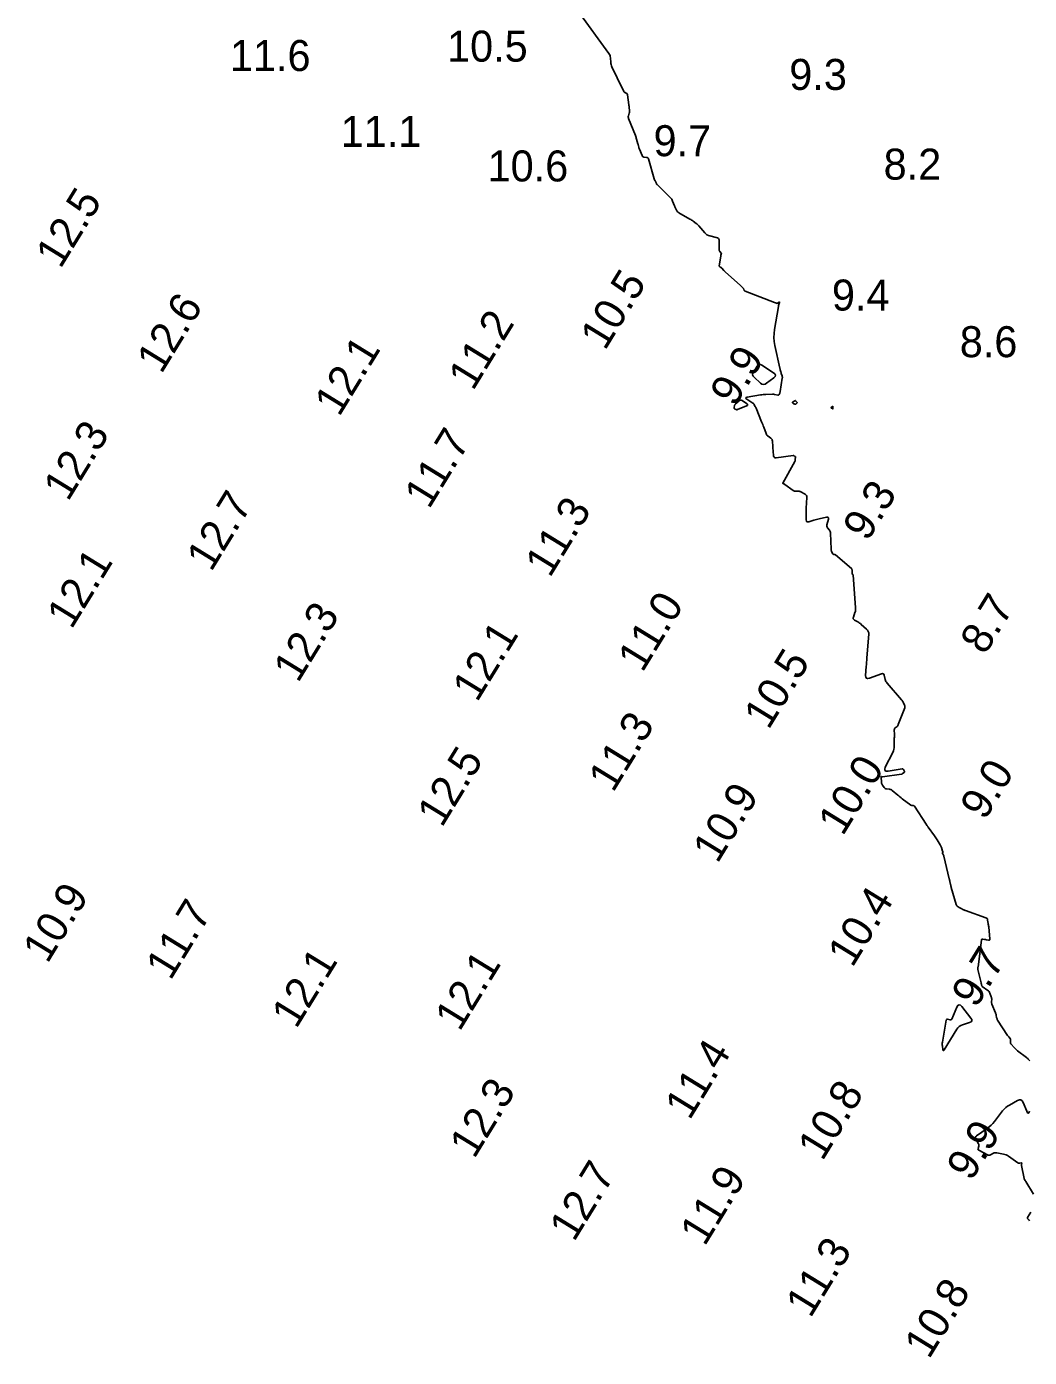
# Model space of a CAD drawing. Extents: x 1023796 to 1112670, y 656573 to 837340.
# Drawn here: x 1100712.2 to 1100873.9, y 687638.2 to 687852.9 of the extents above; entities that cross this region are included whole.
import ezdxf

# ---------------------------------------------------------------- set-up
doc = ezdxf.new("R2010")
doc.units = 0
doc.layers.add('V-CHAN-CONT-10FT', color=7, linetype='Continuous')
doc.layers.add('V-TOPO-SOUN', color=7, linetype='Continuous')

msp = doc.modelspace()

# ---------------------------------------------------------------- linework, layer by layer
at = {"layer": 'V-CHAN-CONT-10FT'}
for points in [[(1100874.02, 687686.03), (1100873.73, 687686.33), (1100873.67, 687686.39), (1100873.61, 687686.45), (1100873.54, 687686.51), (1100873.48, 687686.57), (1100872.04, 687687.67), (1100871.9, 687687.78), (1100871.77, 687687.89), (1100871.65, 687688.01), (1100871.54, 687688.14), (1100870.96, 687688.8), (1100870.91, 687688.86), (1100870.89, 687688.93), (1100870.87, 687689), (1100870.88, 687689.07), (1100870.92, 687689.38), (1100870.92, 687689.46), (1100870.91, 687689.52), (1100870.88, 687689.59), (1100870.83, 687689.65), (1100870.61, 687689.89), (1100870.55, 687689.95), (1100870.5, 687690.01), (1100870.45, 687690.07), (1100870.41, 687690.14), (1100868.81, 687692.62), (1100868.76, 687692.71), (1100868.72, 687692.8), (1100868.69, 687692.9), (1100868.66, 687692.99), (1100868.58, 687693.39), (1100868.56, 687693.49), (1100868.53, 687693.59), (1100868.5, 687693.68), (1100868.46, 687693.78), (1100867.9, 687695.17), (1100867.87, 687695.27), (1100867.85, 687695.36), (1100867.84, 687695.46), (1100867.84, 687695.56), (1100867.86, 687695.96), (1100867.86, 687696.06), (1100867.85, 687696.16), (1100867.83, 687696.25), (1100867.8, 687696.35), (1100867.58, 687696.96), (1100867.53, 687697.08), (1100867.45, 687697.2), (1100867.37, 687697.3), (1100867.26, 687697.39), (1100866.34, 687698.05), (1100866.3, 687698.08), (1100866.27, 687698.12), (1100866.25, 687698.17), (1100866.23, 687698.22), (1100866.2, 687698.43), (1100866.19, 687698.48), (1100866.19, 687698.53), (1100866.17, 687698.58), (1100866.16, 687698.63), (1100865.64, 687700.76), (1100865.62, 687700.83), (1100865.62, 687700.89), (1100865.62, 687700.96), (1100865.63, 687701.03), (1100865.69, 687701.3), (1100865.7, 687701.36), (1100865.72, 687701.43), (1100865.73, 687701.5), (1100865.74, 687701.57), (1100866.23, 687705.55), (1100866.24, 687705.62), (1100866.28, 687705.66), (1100866.33, 687705.68), (1100866.39, 687705.68), (1100866.69, 687705.62), (1100866.76, 687705.61), (1100866.83, 687705.6), (1100866.91, 687705.58), (1100866.98, 687705.57), (1100867.4, 687705.49), (1100867.48, 687705.49), (1100867.53, 687705.51), (1100867.56, 687705.57), (1100867.56, 687705.65), (1100867.38, 687707.65), (1100867.36, 687707.79), (1100867.34, 687707.93), (1100867.32, 687708.06), (1100867.3, 687708.2), (1100867.21, 687708.75), (1100867.17, 687708.88), (1100867.11, 687708.98), (1100867.02, 687709.06), (1100866.9, 687709.12), (1100863.65, 687710.26), (1100863.56, 687710.29), (1100863.46, 687710.33), (1100863.38, 687710.37), (1100863.29, 687710.41), (1100862.92, 687710.6), (1100862.85, 687710.65), (1100862.77, 687710.69), (1100862.69, 687710.74), (1100862.62, 687710.79), (1100862.32, 687710.99), (1100862.25, 687711.05), (1100862.2, 687711.11), (1100862.16, 687711.19), (1100862.13, 687711.27), (1100861.35, 687714), (1100861.32, 687714.11), (1100861.29, 687714.23), (1100861.26, 687714.35), (1100861.23, 687714.46), (1100861.13, 687714.94), (1100861.1, 687715.05), (1100861.08, 687715.17), (1100861.05, 687715.29), (1100861.02, 687715.41), (1100860.17, 687719.05), (1100860.16, 687719.09), (1100860.14, 687719.14), (1100860.12, 687719.18), (1100860.09, 687719.22), (1100859.97, 687719.4), (1100859.95, 687719.43), (1100859.94, 687719.47), (1100859.93, 687719.51), (1100859.94, 687719.55), (1100859.96, 687719.71), (1100859.97, 687719.75), (1100859.97, 687719.79), (1100859.96, 687719.83), (1100859.95, 687719.87), (1100859.75, 687720.44), (1100859.71, 687720.55), (1100859.66, 687720.66), (1100859.61, 687720.76), (1100859.56, 687720.86), (1100859.07, 687721.69), (1100858.97, 687721.86), (1100858.87, 687722.03), (1100858.76, 687722.19), (1100858.64, 687722.35), (1100857.62, 687723.72), (1100857.61, 687723.75), (1100857.59, 687723.77), (1100857.57, 687723.8), (1100857.55, 687723.82), (1100857.46, 687723.93), (1100857.45, 687723.95), (1100857.43, 687723.97), (1100857.42, 687724), (1100857.41, 687724.02), (1100857.37, 687724.12), (1100857.36, 687724.14), (1100857.35, 687724.17), (1100857.33, 687724.19), (1100857.32, 687724.21), (1100855.4, 687727.1), (1100855.37, 687727.14), (1100855.33, 687727.17), (1100855.28, 687727.19), (1100855.23, 687727.2), (1100855.02, 687727.22), (1100854.96, 687727.23), (1100854.91, 687727.24), (1100854.87, 687727.27), (1100854.82, 687727.29), (1100853.44, 687728.32), (1100853.26, 687728.47), (1100853.07, 687728.61), (1100852.88, 687728.76), (1100852.7, 687728.91), (1100851.8, 687729.66), (1100851.7, 687729.73), (1100851.6, 687729.78), (1100851.49, 687729.82), (1100851.38, 687729.84), (1100850.9, 687729.89), (1100850.79, 687729.92), (1100850.69, 687729.96), (1100850.6, 687730.03), (1100850.52, 687730.11), (1100850.25, 687730.5), (1100850.19, 687730.6), (1100850.14, 687730.7), (1100850.11, 687730.81), (1100850.09, 687730.93), (1100850.01, 687731.87), (1100850.01, 687731.9), (1100850.02, 687731.91), (1100850.03, 687731.91), (1100850.06, 687731.9), (1100850.16, 687731.85), (1100850.18, 687731.83), (1100850.21, 687731.83), (1100850.24, 687731.82), (1100850.26, 687731.83), (1100853.3, 687732.28), (1100853.36, 687732.29), (1100853.41, 687732.31), (1100853.46, 687732.33), (1100853.5, 687732.36), (1100853.74, 687732.55), (1100853.75, 687732.55), (1100853.76, 687732.57), (1100853.77, 687732.58), (1100853.78, 687732.59), (1100853.81, 687732.64), (1100853.82, 687732.65), (1100853.82, 687732.66), (1100853.82, 687732.68), (1100853.82, 687732.69), (1100853.62, 687733.02), (1100853.58, 687733.07), (1100853.53, 687733.11), (1100853.48, 687733.12), (1100853.41, 687733.12), (1100851.14, 687732.78), (1100850.82, 687732.77), (1100850.63, 687732.87), (1100850.6, 687733.08), (1100850.7, 687733.39), (1100851.9, 687735.79), (1100852, 687736.03), (1100852.07, 687736.28), (1100852.12, 687736.53), (1100852.14, 687736.79), (1100852.15, 687738.07), (1100852.16, 687738.22), (1100852.16, 687738.38), (1100852.16, 687738.53), (1100852.16, 687738.69), (1100852.15, 687739.43), (1100852.16, 687739.52), (1100852.19, 687739.6), (1100852.24, 687739.67), (1100852.3, 687739.73), (1100852.59, 687739.97), (1100852.66, 687740.03), (1100852.72, 687740.1), (1100852.76, 687740.17), (1100852.8, 687740.26), (1100853.83, 687742.97), (1100853.87, 687743.09), (1100853.87, 687743.2), (1100853.85, 687743.31), (1100853.81, 687743.42), (1100853.59, 687743.86), (1100853.53, 687743.97), (1100853.47, 687744.07), (1100853.4, 687744.17), (1100853.32, 687744.27), (1100850.99, 687746.96), (1100850.89, 687747.1), (1100850.8, 687747.24), (1100850.73, 687747.4), (1100850.68, 687747.56), (1100850.52, 687748.24), (1100850.46, 687748.38), (1100850.38, 687748.46), (1100850.26, 687748.49), (1100850.11, 687748.46), (1100848.14, 687747.75), (1100847.85, 687747.69), (1100847.65, 687747.75), (1100847.55, 687747.92), (1100847.53, 687748.21), (1100847.63, 687749.62), (1100847.66, 687749.97), (1100847.68, 687750.32), (1100847.71, 687750.67), (1100847.74, 687751.02), (1100848.02, 687754.83), (1100848.02, 687755.07), (1100847.96, 687755.29), (1100847.85, 687755.49), (1100847.69, 687755.66), (1100846.81, 687756.44), (1100846.69, 687756.55), (1100846.56, 687756.65), (1100846.43, 687756.74), (1100846.29, 687756.82), (1100845.73, 687757.14), (1100845.61, 687757.23), (1100845.54, 687757.34), (1100845.52, 687757.47), (1100845.55, 687757.61), (1100845.81, 687758.36), (1100845.87, 687758.53), (1100845.9, 687758.71), (1100845.91, 687758.9), (1100845.91, 687759.08), (1100845.51, 687764.4), (1100845.5, 687764.42), (1100845.49, 687764.45), (1100845.48, 687764.46), (1100845.46, 687764.48), (1100845.38, 687764.53), (1100845.36, 687764.54), (1100845.34, 687764.56), (1100845.34, 687764.58), (1100845.34, 687764.61), (1100845.36, 687765.12), (1100845.36, 687765.22), (1100845.33, 687765.3), (1100845.29, 687765.37), (1100845.23, 687765.44), (1100842.66, 687767.65), (1100842.63, 687767.68), (1100842.6, 687767.7), (1100842.56, 687767.71), (1100842.52, 687767.71), (1100842.36, 687767.72), (1100842.32, 687767.72), (1100842.29, 687767.74), (1100842.26, 687767.76), (1100842.24, 687767.79), (1100842.04, 687768.2), (1100842.01, 687768.28), (1100841.98, 687768.36), (1100841.96, 687768.45), (1100841.96, 687768.54), (1100841.86, 687771.15), (1100841.85, 687771.28), (1100841.81, 687771.4), (1100841.76, 687771.51), (1100841.69, 687771.62), (1100841.37, 687772.03), (1100841.31, 687772.13), (1100841.27, 687772.25), (1100841.26, 687772.36), (1100841.28, 687772.49), (1100841.52, 687773.39), (1100841.54, 687773.56), (1100841.5, 687773.66), (1100841.4, 687773.71), (1100841.23, 687773.7), (1100840.02, 687773.45), (1100839.81, 687773.4), (1100839.6, 687773.35), (1100839.39, 687773.29), (1100839.18, 687773.23), (1100838.35, 687772.98), (1100838.17, 687772.95), (1100838.05, 687772.99), (1100837.97, 687773.1), (1100837.94, 687773.28), (1100837.94, 687774.25), (1100837.94, 687774.49), (1100837.95, 687774.72), (1100837.95, 687774.96), (1100837.96, 687775.19), (1100838.05, 687776.89), (1100838.04, 687777.06), (1100837.98, 687777.2), (1100837.89, 687777.32), (1100837.75, 687777.42), (1100836.98, 687777.85), (1100836.89, 687777.89), (1100836.8, 687777.92), (1100836.71, 687777.93), (1100836.61, 687777.93), (1100836.22, 687777.9), (1100836.12, 687777.9), (1100836.03, 687777.92), (1100835.95, 687777.95), (1100835.86, 687778.01), (1100834.51, 687779.02), (1100834.48, 687779.04), (1100834.44, 687779.06), (1100834.41, 687779.07), (1100834.38, 687779.09), (1100834.23, 687779.13), (1100834.2, 687779.14), (1100834.19, 687779.16), (1100834.19, 687779.19), (1100834.2, 687779.22), (1100836.11, 687782.69), (1100836.14, 687782.77), (1100836.17, 687782.84), (1100836.18, 687782.92), (1100836.19, 687783), (1100836.21, 687783.46), (1100836.21, 687783.47), (1100836.2, 687783.49), (1100836.19, 687783.49), (1100836.17, 687783.5), (1100836.1, 687783.51), (1100836.08, 687783.51), (1100836.06, 687783.52), (1100836.04, 687783.53), (1100836.03, 687783.54), (1100835.94, 687783.65), (1100835.92, 687783.67), (1100835.9, 687783.68), (1100835.87, 687783.69), (1100835.84, 687783.69), (1100833.1, 687783.31), (1100832.93, 687783.31), (1100832.81, 687783.37), (1100832.73, 687783.47), (1100832.69, 687783.63), (1100832.62, 687784.37), (1100832.6, 687784.55), (1100832.58, 687784.74), (1100832.57, 687784.92), (1100832.56, 687785.11), (1100832.5, 687786.01), (1100832.48, 687786.14), (1100832.43, 687786.26), (1100832.36, 687786.36), (1100832.26, 687786.45), (1100831.81, 687786.78), (1100831.71, 687786.87), (1100831.62, 687786.97), (1100831.54, 687787.08), (1100831.49, 687787.21), (1100831.1, 687788.23), (1100831.01, 687788.45), (1100830.93, 687788.66), (1100830.85, 687788.87), (1100830.76, 687789.08), (1100829.85, 687791.32), (1100829.82, 687791.39), (1100829.79, 687791.46), (1100829.76, 687791.53), (1100829.72, 687791.6), (1100829.57, 687791.87), (1100829.53, 687791.94), (1100829.48, 687791.99), (1100829.42, 687792.05), (1100829.36, 687792.09), (1100828.35, 687792.77), (1100828.22, 687792.88), (1100828.18, 687792.97), (1100828.25, 687793.04), (1100828.42, 687793.09), (1100830.57, 687793.44), (1100830.78, 687793.47), (1100830.99, 687793.49), (1100831.2, 687793.51), (1100831.42, 687793.52), (1100832.49, 687793.55), (1100832.59, 687793.55), (1100832.7, 687793.55), (1100832.8, 687793.53), (1100832.9, 687793.51), (1100833.38, 687793.41), (1100833.44, 687793.4), (1100833.49, 687793.41), (1100833.53, 687793.45), (1100833.56, 687793.5), (1100833.67, 687793.75), (1100833.7, 687793.81), (1100833.72, 687793.88), (1100833.74, 687793.95), (1100833.75, 687794.01), (1100834.09, 687796.13), (1100834.1, 687796.23), (1100834.1, 687796.32), (1100834.09, 687796.41), (1100834.06, 687796.5), (1100833.93, 687796.9), (1100833.91, 687796.97), (1100833.88, 687797.04), (1100833.86, 687797.11), (1100833.84, 687797.19), (1100833.76, 687797.48), (1100833.74, 687797.55), (1100833.72, 687797.63), (1100833.71, 687797.7), (1100833.69, 687797.78), (1100832.88, 687801.43), (1100832.78, 687802.07), (1100832.73, 687802.7), (1100832.75, 687803.34), (1100832.82, 687803.98), (1100833.46, 687807.72), (1100833.47, 687807.8), (1100833.49, 687807.88), (1100833.51, 687807.95), (1100833.54, 687808.03), (1100833.64, 687808.36), (1100833.65, 687808.41), (1100833.64, 687808.44), (1100833.61, 687808.44), (1100833.57, 687808.41), (1100833.31, 687808.23), (1100833.27, 687808.21), (1100833.23, 687808.2), (1100833.19, 687808.2), (1100833.15, 687808.22), (1100832.99, 687808.29), (1100832.95, 687808.31), (1100832.91, 687808.33), (1100832.86, 687808.35), (1100832.82, 687808.37), (1100828.08, 687810.18), (1100828.03, 687810.2), (1100828, 687810.22), (1100827.97, 687810.26), (1100827.95, 687810.3), (1100827.88, 687810.48), (1100827.86, 687810.52), (1100827.83, 687810.57), (1100827.81, 687810.61), (1100827.78, 687810.64), (1100827.53, 687810.93), (1100827.47, 687810.98), (1100827.42, 687811.04), (1100827.36, 687811.1), (1100827.3, 687811.15), (1100824.93, 687813.26), (1100824.86, 687813.32), (1100824.79, 687813.39), (1100824.73, 687813.46), (1100824.66, 687813.53), (1100824.36, 687813.89), (1100824.32, 687813.93), (1100824.28, 687813.97), (1100824.24, 687814), (1100824.19, 687814.02), (1100823.99, 687814.12), (1100823.95, 687814.15), (1100823.92, 687814.19), (1100823.91, 687814.23), (1100823.91, 687814.28), (1100824.16, 687815.8), (1100824.17, 687815.84), (1100824.18, 687815.89), (1100824.19, 687815.93), (1100824.2, 687815.98), (1100824.25, 687816.16), (1100824.26, 687816.2), (1100824.26, 687816.24), (1100824.24, 687816.28), (1100824.22, 687816.32), (1100824.01, 687816.58), (1100823.97, 687816.63), (1100823.94, 687816.7), (1100823.92, 687816.76), (1100823.92, 687816.83), (1100823.92, 687818.24), (1100823.88, 687818.47), (1100823.79, 687818.65), (1100823.63, 687818.78), (1100823.41, 687818.86), (1100822.4, 687819.08), (1100822.16, 687819.15), (1100821.94, 687819.26), (1100821.74, 687819.41), (1100821.57, 687819.59), (1100820.64, 687820.7), (1100820.54, 687820.82), (1100820.43, 687820.92), (1100820.32, 687821.02), (1100820.2, 687821.11), (1100819.71, 687821.47), (1100819.58, 687821.56), (1100819.45, 687821.64), (1100819.33, 687821.72), (1100819.2, 687821.8), (1100817.39, 687822.84), (1100817.29, 687822.9), (1100817.21, 687822.98), (1100817.14, 687823.06), (1100817.09, 687823.15), (1100816.88, 687823.56), (1100816.83, 687823.66), (1100816.78, 687823.76), (1100816.73, 687823.87), (1100816.69, 687823.97), (1100816.4, 687824.71), (1100816.33, 687824.86), (1100816.25, 687825), (1100816.15, 687825.13), (1100816.04, 687825.26), (1100813.89, 687827.37), (1100813.85, 687827.41), (1100813.82, 687827.46), (1100813.79, 687827.5), (1100813.77, 687827.55), (1100813.69, 687827.77), (1100813.67, 687827.82), (1100813.65, 687827.86), (1100813.63, 687827.91), (1100813.6, 687827.95), (1100813.49, 687828.12), (1100813.46, 687828.16), (1100813.44, 687828.2), (1100813.42, 687828.25), (1100813.4, 687828.3), (1100812.5, 687831.52), (1100812.46, 687831.62), (1100812.4, 687831.69), (1100812.32, 687831.74), (1100812.21, 687831.76), (1100811.77, 687831.82), (1100811.67, 687831.84), (1100811.58, 687831.89), (1100811.51, 687831.96), (1100811.46, 687832.05), (1100811.03, 687833.07), (1100811.01, 687833.14), (1100810.98, 687833.21), (1100810.96, 687833.28), (1100810.94, 687833.35), (1100810.87, 687833.65), (1100810.85, 687833.72), (1100810.84, 687833.79), (1100810.82, 687833.87), (1100810.8, 687833.94), (1100810.59, 687834.69), (1100810.54, 687834.84), (1100810.5, 687834.99), (1100810.45, 687835.14), (1100810.39, 687835.28), (1100809.29, 687838.03), (1100809.26, 687838.13), (1100809.25, 687838.24), (1100809.25, 687838.35), (1100809.27, 687838.46), (1100809.39, 687838.89), (1100809.42, 687839), (1100809.43, 687839.12), (1100809.44, 687839.23), (1100809.43, 687839.34), (1100809.39, 687839.8), (1100809.38, 687839.92), (1100809.37, 687840.03), (1100809.35, 687840.15), (1100809.34, 687840.26), (1100809.14, 687841.87), (1100809.12, 687841.94), (1100809.09, 687842), (1100809.04, 687842.04), (1100808.98, 687842.08), (1100808.72, 687842.21), (1100808.65, 687842.25), (1100808.6, 687842.29), (1100808.55, 687842.35), (1100808.52, 687842.41), (1100807.71, 687844.07), (1100807.58, 687844.34), (1100807.45, 687844.6), (1100807.33, 687844.86), (1100807.2, 687845.13), (1100806.61, 687846.38), (1100806.54, 687846.55), (1100806.48, 687846.73), (1100806.45, 687846.9), (1100806.42, 687847.09), (1100806.37, 687847.83), (1100806.35, 687848.01), (1100806.3, 687848.18), (1100806.22, 687848.34), (1100806.13, 687848.5), (1100801.09, 687855.42)], [(1100874.63, 687664.53), (1100873.35, 687666.58), (1100873.33, 687666.62), (1100873.31, 687666.66), (1100873.28, 687666.69), (1100873.25, 687666.73), (1100873.15, 687666.88), (1100873.13, 687666.91), (1100873.11, 687666.95), (1100873.09, 687666.99), (1100873.08, 687667.04), (1100872.69, 687669.16), (1100872.68, 687669.2), (1100872.68, 687669.25), (1100872.68, 687669.29), (1100872.69, 687669.33), (1100872.73, 687669.51), (1100872.74, 687669.55), (1100872.73, 687669.57), (1100872.7, 687669.59), (1100872.66, 687669.58), (1100872.35, 687669.52), (1100872.28, 687669.52), (1100872.22, 687669.53), (1100872.15, 687669.55), (1100872.1, 687669.58), (1100870.58, 687670.64), (1100870.39, 687670.76), (1100870.19, 687670.86), (1100869.97, 687670.93), (1100869.75, 687670.99), (1100868.67, 687671.2), (1100868.53, 687671.21), (1100868.4, 687671.2), (1100868.28, 687671.17), (1100868.15, 687671.12), (1100867.67, 687670.88), (1100867.54, 687670.84), (1100867.42, 687670.82), (1100867.3, 687670.84), (1100867.18, 687670.89), (1100865.78, 687671.62), (1100865.7, 687671.68), (1100865.66, 687671.74), (1100865.64, 687671.82), (1100865.66, 687671.91), (1100865.78, 687672.29), (1100865.8, 687672.39), (1100865.8, 687672.48), (1100865.78, 687672.57), (1100865.74, 687672.66), (1100865.3, 687673.42), (1100865.24, 687673.57), (1100865.24, 687673.7), (1100865.3, 687673.83), (1100865.41, 687673.94), (1100867.13, 687675.13), (1100867.46, 687675.38), (1100867.76, 687675.64), (1100868.04, 687675.93), (1100868.3, 687676.25), (1100869.62, 687677.96), (1100869.86, 687678.24), (1100870.12, 687678.49), (1100870.41, 687678.71), (1100870.73, 687678.91), (1100872.03, 687679.62), (1100872.33, 687679.74), (1100872.59, 687679.72), (1100872.8, 687679.57), (1100872.96, 687679.29), (1100873.51, 687677.91), (1100873.64, 687677.65), (1100873.76, 687677.57), (1100873.86, 687677.67), (1100873.95, 687677.94)], [(1100873.98, 687660.25), (1100873.92, 687660.31), (1100873.68, 687660.53), (1100873.64, 687660.59), (1100873.62, 687660.65), (1100873.62, 687660.72), (1100873.65, 687660.79), (1100874.18, 687661.63)]]:
    msp.add_lwpolyline(points, dxfattribs=at)
for points in [[(1100830.35, 687798.36), (1100830.55, 687798.35), (1100830.77, 687798.25), (1100832.68, 687797.01), (1100832.9, 687796.82), (1100832.98, 687796.62), (1100832.92, 687796.41), (1100832.71, 687796.2), (1100831.56, 687795.32), (1100831.3, 687795.18), (1100831.05, 687795.14), (1100830.8, 687795.2), (1100830.56, 687795.36), (1100829.53, 687796.3), (1100829.37, 687796.49), (1100829.3, 687796.7), (1100829.31, 687796.92), (1100829.42, 687797.14), (1100830.01, 687798.08), (1100830.17, 687798.27)], [(1100826.43, 687791.85), (1100826.46, 687791.89), (1100826.5, 687791.93), (1100827.11, 687792.5), (1100827.23, 687792.59), (1100827.35, 687792.62), (1100827.48, 687792.61), (1100827.61, 687792.54), (1100828.34, 687792.06), (1100828.46, 687791.95), (1100828.5, 687791.85), (1100828.45, 687791.76), (1100828.31, 687791.68), (1100826.88, 687791.08), (1100826.82, 687791.06), (1100826.77, 687791.05), (1100826.71, 687791.06), (1100826.66, 687791.08), (1100826.36, 687791.22), (1100826.35, 687791.23), (1100826.34, 687791.25), (1100826.33, 687791.26), (1100826.33, 687791.28), (1100826.32, 687791.36), (1100826.32, 687791.38), (1100826.33, 687791.4), (1100826.33, 687791.42), (1100826.33, 687791.44), (1100826.39, 687791.74), (1100826.4, 687791.8)], [(1100836.47, 687792.19), (1100836.46, 687792.16), (1100836.43, 687792.12), (1100836.25, 687791.98), (1100836.22, 687791.96), (1100836.19, 687791.95), (1100836.16, 687791.95), (1100836.12, 687791.96), (1100835.98, 687792), (1100835.94, 687792.01), (1100835.91, 687792.02), (1100835.88, 687792.04), (1100835.85, 687792.06), (1100835.73, 687792.17), (1100835.71, 687792.19), (1100835.71, 687792.22), (1100835.72, 687792.24), (1100835.74, 687792.26), (1100836.11, 687792.49), (1100836.15, 687792.52), (1100836.2, 687792.52), (1100836.24, 687792.5), (1100836.28, 687792.46), (1100836.44, 687792.26), (1100836.46, 687792.23)], [(1100842.23, 687791.6), (1100842.25, 687791.58), (1100842.26, 687791.54), (1100842.26, 687791.23), (1100842.26, 687791.21), (1100842.25, 687791.2), (1100842.24, 687791.19), (1100842.21, 687791.21), (1100842.07, 687791.3), (1100842.06, 687791.31), (1100842.06, 687791.31), (1100842.05, 687791.31), (1100842.05, 687791.3), (1100842.03, 687791.29), (1100842.02, 687791.29), (1100842.02, 687791.29), (1100842.01, 687791.29), (1100842.01, 687791.29), (1100841.96, 687791.38), (1100841.95, 687791.4), (1100841.95, 687791.41), (1100841.96, 687791.42), (1100841.97, 687791.43), (1100842.18, 687791.58), (1100842.21, 687791.6)], [(1100864.66, 687692.49), (1100864.55, 687692.34), (1100864.31, 687692.23), (1100863.13, 687691.85), (1100862.86, 687691.74), (1100862.61, 687691.58), (1100862.4, 687691.38), (1100862.22, 687691.14), (1100860.2, 687687.79), (1100860.13, 687687.7), (1100860.07, 687687.68), (1100860.03, 687687.72), (1100860, 687687.83), (1100859.91, 687688.43), (1100859.89, 687688.58), (1100859.89, 687688.72), (1100859.9, 687688.87), (1100859.91, 687689.02), (1100860.53, 687692.58), (1100860.55, 687692.66), (1100860.6, 687692.72), (1100860.66, 687692.74), (1100860.75, 687692.73), (1100861.14, 687692.64), (1100861.23, 687692.63), (1100861.3, 687692.65), (1100861.36, 687692.7), (1100861.41, 687692.78), (1100862.25, 687694.71), (1100862.42, 687694.98), (1100862.6, 687695.09), (1100862.81, 687695.03), (1100863.03, 687694.81), (1100864.52, 687692.9), (1100864.65, 687692.68)]]:
    msp.add_lwpolyline(points, close=True, dxfattribs=at)

# ---------------------------------------------------------------- texts
at = {"layer": 'V-TOPO-SOUN'}
for s, p in [('10.5 ', (1100780.01, 687847.2)), ('11.6 ', (1100744.98, 687845.69)), ('9.3', (1100835.21, 687842.64)), ('11.1 ', (1100762.86, 687833.46)), ('9.7', (1100813.32, 687831.95)), ('10.6 ', (1100786.55, 687827.88)), ('8.2', (1100850.43, 687828.17)), ('9.4', (1100842.09, 687807.05)), ('8.6', (1100862.71, 687799.53))]:
    msp.add_text(s, height=5, dxfattribs=at).set_placement(p)
for s, p in [('12.5 ', (1100717.65, 687813.65)), ('10.5 ', (1100805.48, 687800.46)), ('12.6 ', (1100733.93, 687796.69)), ('11.2 ', (1100784.19, 687793.97)), ('12.1 ', (1100762.6, 687789.78)), ('9.9', (1100826.41, 687791.37)), ('12.3 ', (1100718.87, 687776.12)), ('11.7 ', (1100777.1, 687774.88)), ('9.3', (1100847.83, 687769.66)), ('12.7 ', (1100741.96, 687764.77)), ('11.3 ', (1100796.59, 687763.82)), ('12.1 ', (1100719.43, 687755.49)), ('11.0 ', (1100811.52, 687748.53)), ('8.7', (1100866.76, 687751.35)), ('12.3 ', (1100755.97, 687746.86)), ('12.1 ', (1100784.85, 687743.75)), ('10.5 ', (1100831.86, 687739.3)), ('11.3 ', (1100806.79, 687729.17)), ('12.5 ', (1100779.17, 687723.52)), ('10.0 ', (1100843.83, 687722.15)), ('9.0', (1100866.75, 687724.67)), ('10.9 ', (1100823.62, 687717.72)), ('10.9 ', (1100715.55, 687701.58)), ('10.4 ', (1100845.38, 687700.93)), ('11.7 ', (1100735.4, 687698.86)), ('12.1 ', (1100755.68, 687691.06)), ('12.1 ', (1100782.03, 687690.63)), ('9.7', (1100865.35, 687694.39)), ('11.4 ', (1100819.13, 687676.32)), ('12.3 ', (1100784.39, 687670.09)), ('10.8 ', (1100840.55, 687669.73)), ('9.9', (1100864.56, 687666.47)), ('12.7 ', (1100800.49, 687656.7)), ('11.9 ', (1100821.56, 687655.98)), ('11.3 ', (1100838.62, 687644.4)), ('10.8 ', (1100857.74, 687637.77))]:
    msp.add_text(s, height=5, rotation=58.4285, dxfattribs=at).set_placement(p)

doc.saveas('drawing.dxf')
